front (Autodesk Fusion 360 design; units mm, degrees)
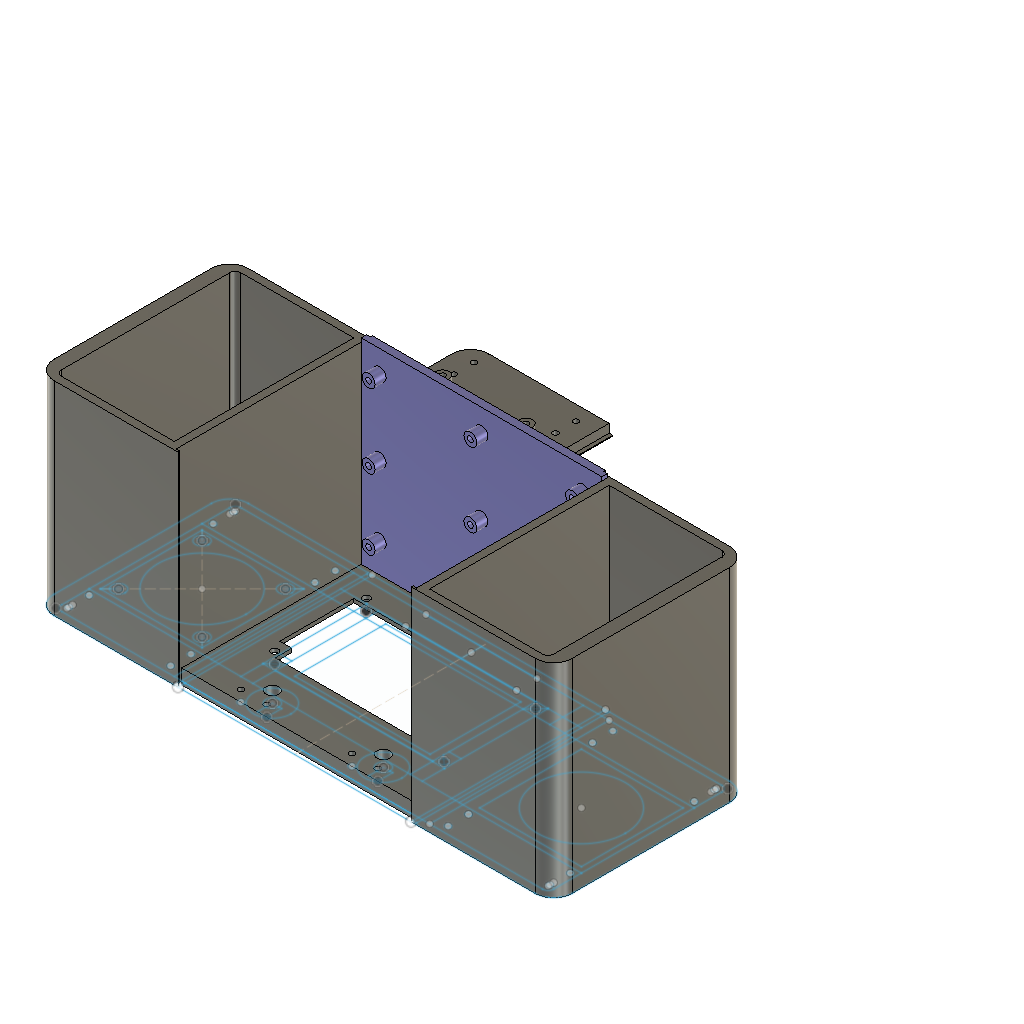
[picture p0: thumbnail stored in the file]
part number: 2026-10-08-07-20-58-243
sketch "Sketch1" plane through (0, 0, 0) normal (0, 0, 1) x axis (1, 0, 0)
  line L1 (260, -5) -> (20, -5)
  line L2 (270, -100) -> (270, -15)
  line L3 (20, -110) -> (260, -110)
  line L4 (210, -30) -> (265, -30)
  line L5 (210, -85) -> (210, -30)
  line L6 (265, -85) -> (210, -85)
  line L7 (265, -30) -> (265, -85)
  line L8 (70, -30) -> (15, -30)
  line L9 (70, -85) -> (70, -30)
  line L10 (15, -85) -> (70, -85)
  line L11 (15, -30) -> (15, -85)
  line L12 (187, -20) -> (89, -20)
  line L13 (187, -76) -> (187, -20)
  line L14 (89, -76) -> (187, -76)
  line L15 (89, -20) -> (89, -76)
  curve K1
  curve K2
  curve K3
  curve K4
  line L16 (95.5, -75.75) -> (180.5, -75.75)
  line L17 (95.5, -20.25) -> (95.5, -75.75)
  line L18 (180.5, -20.25) -> (95.5, -20.25)
  line L19 (180.5, -75.75) -> (180.5, -20.25)
  line L20 (176.5, -24.25) -> (103.5, -24.25)
  line L21 (176.5, -73.25) -> (176.5, -24.25)
  line L22 (103.5, -73.25) -> (176.5, -73.25)
  line L23 (103.5, -24.25) -> (103.5, -73.25)
  line L24 (10, -100) -> (10, -15)
  line L25 (140, -5) -> (140, -110)
  line L26 (75, -110) -> (75, -5)
  line L27 (205, -110) -> (205, -5)
  line L28 (77, -110) -> (77, -5)
  line L29 (203, -110) -> (203, -5)
  line L30 (203, -7) -> (77, -7)
  line L31 (203, -108) -> (77, -108)
  line L32 (70, -85) -> (15, -30)
  line L33 (70, -30) -> (15, -85)
  line L34 (19.9497, -34.9497) -> (15, -30)
  line L35 (65.0503, -34.9497) -> (70, -30)
  line L36 (19.9497, -80.0503) -> (15, -85)
  line L37 (65.0503, -80.0503) -> (70, -85)
  line L38 (176.5, -164.25) -> (103.5, -164.25)
  curve K5
  curve K6
  curve K7
  curve K8
  line L39 (187, -160) -> (89, -160)
  line L40 (14.9497, -174.9497) -> (10, -170)
  line L41 (14.9497, -220.0503) -> (10, -225)
  line L42 (65, -225) -> (65, -170)
  line L43 (60.0503, -220.0503) -> (65, -225)
  line L44 (95.5, -215.75) -> (180.5, -215.75)
  line L45 (203, -248) -> (77, -248)
  line L46 (270, -145) -> (10, -145)
  line L47 (10, -250) -> (270, -250)
  line L48 (103.5, -213.25) -> (176.5, -213.25)
  line L49 (77, -250) -> (77, -145)
  line L50 (180.5, -160.25) -> (95.5, -160.25)
  line L51 (203, -147) -> (77, -147)
  line L52 (89, -216) -> (187, -216)
  line L53 (10, -225) -> (65, -225)
  line L54 (215, -170) -> (270, -170)
  line L55 (75, -250) -> (75, -145)
  line L56 (65, -225) -> (10, -170)
  line L57 (95.5, -160.25) -> (95.5, -215.75)
  line L58 (176.5, -213.25) -> (176.5, -164.25)
  line L59 (140, -145) -> (140, -250)
  line L60 (205, -250) -> (205, -145)
  line L61 (270, -225) -> (215, -225)
  line L62 (103.5, -164.25) -> (103.5, -213.25)
  line L63 (0, -240) -> (0, -155)
  line L64 (187, -216) -> (187, -160)
  line L65 (89, -160) -> (89, -216)
  line L66 (65, -170) -> (10, -170)
  line L67 (60.0503, -174.9497) -> (65, -170)
  line L68 (65, -170) -> (10, -225)
  line L69 (203, -250) -> (203, -145)
  line L70 (10, -170) -> (10, -225)
  line L71 (280, -240) -> (280, -155)
  line L72 (215, -225) -> (215, -170)
  line L73 (180.5, -215.75) -> (180.5, -160.25)
  line L74 (270, -170) -> (270, -225)
  circle C1 centre (165, -92) radius 10
  circle C2 centre (115, -92) radius 10
  circle C3 centre (42.5, -57.5) radius 23.75
  circle C4 centre (237.5, -57.5) radius 23.75
  circle C5 centre (165, -92) radius 3.5
  circle C6 centre (115, -92) radius 3.5
  arc A1 centre (20, -15) radius 10 clockwise from (10, -15) to (20, -5)
  arc A2 centre (20, -100) radius 10 clockwise from (20, -110) to (10, -100)
  arc A3 centre (260, -100) radius 10 clockwise from (270, -100) to (260, -110)
  arc A4 centre (260, -15) radius 10 clockwise from (260, -5) to (270, -15)
  circle C7 centre (19.9497, -34.9497) radius 1.5
  circle C8 centre (65.0503, -34.9497) radius 1.5
  circle C9 centre (19.9497, -80.0503) radius 1.5
  circle C10 centre (65.0503, -80.0503) radius 1.5
  circle C11 centre (19.9497, -80.0503) radius 3.5
  circle C12 centre (65.0503, -80.0503) radius 3.5
  circle C13 centre (65.0503, -34.9497) radius 3.5
  circle C14 centre (19.9497, -34.9497) radius 3.5
  circle C15 centre (65, -102) radius 1.5
  circle C16 centre (20, -102) radius 1.5
  circle C17 centre (65, -91) radius 1.5
  circle C18 centre (20, -91) radius 1.5
  circle C19 centre (65, -13) radius 1.5
  circle C20 centre (20, -13) radius 1.5
  circle C21 centre (20, -24) radius 1.5
  circle C22 centre (65, -24) radius 1.5
  circle C23 centre (60.0503, -174.9497) radius 3.5
  circle C24 centre (65, -164) radius 1.5
  circle C25 centre (60.0503, -220.0503) radius 1.5
  circle C26 centre (10, -164) radius 1.5
  circle C27 centre (14.9497, -174.9497) radius 3.5
  arc A5 centre (10, -240) radius 10 clockwise from (10, -250) to (0, -240)
  circle C28 centre (10, -231) radius 1.5
  circle C29 centre (14.9497, -220.0503) radius 1.5
  circle C30 centre (10, -242) radius 1.5
  circle C31 centre (14.9497, -174.9497) radius 1.5
  circle C32 centre (14.9497, -220.0503) radius 3.5
  arc A6 centre (10, -155) radius 10 clockwise from (0, -155) to (10, -145)
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  point P40 (140, -110)
  point P41 (140, -5)
  point P42 (75, -5)
  point P43 (75, -110)
  point P44 (205, -5)
  point P45 (205, -110)
  point P50 (77, -7)
  point P51 (203, -7)
  point P52 (77, -108)
  point P53 (203, -108)
  point P54 (19.9497, -34.9497)
  point P58 (19.9497, -34.9497)
  point P55 (65.0503, -34.9497)
  point P59 (65.0503, -34.9497)
  point P56 (19.9497, -80.0503)
  point P60 (19.9497, -80.0503)
  point P57 (65.0503, -80.0503)
  point P61 (65.0503, -80.0503)
  point P97 (140, -250)
  point P98 (140, -145)
  point P122 (75, -145)
  point P123 (75, -250)
  point P103 (205, -145)
  point P146 (205, -250)
  point P137 (77, -147)
  point P136 (203, -147)
  point P92 (77, -248)
  point P124 (203, -248)
  point P85 (14.9497, -174.9497)
  point P119 (14.9497, -174.9497)
  point P86 (60.0503, -174.9497)
  point P120 (60.0503, -174.9497)
  point P87 (14.9497, -220.0503)
  point P147 (14.9497, -220.0503)
  point P77 (60.0503, -220.0503)
  point P117 (60.0503, -220.0503)
  point P2 (265, -30)
  point P3 (210, -30)
  point P5 (265, -85)
  point P6 (15, -30)
  point P7 (70, -30)
  point P9 (15, -85)
  point P10 (89, -20)
  point P11 (187, -20)
  point P13 (89, -76)
  point P22 (95.5, -20.25)
  point P23 (180.5, -20.25)
  point P21 (95.5, -75.75)
  point P24 (103.5, -24.25)
  point P25 (176.5, -24.25)
  point P27 (103.5, -73.25)
  point P8 (70, -85)
  point P93 (270, -170)
  point P94 (215, -170)
  point P96 (270, -225)
  point P88 (10, -170)
  point P89 (65, -170)
  point P91 (10, -225)
  point P80 (187, -160)
  point P84 (89, -160)
  point P81 (89, -216)
  point P76 (180.5, -160.25)
  point P78 (95.5, -160.25)
  point P75 (95.5, -215.75)
  point P130 (103.5, -164.25)
  point P132 (176.5, -164.25)
  point P131 (103.5, -213.25)
  point P90 (65, -225)
  horizontal L1
  vertical L2
  horizontal L4
  vertical L5
  horizontal L6
  vertical L7
  horizontal L8
  vertical L9
  horizontal L10
  vertical L11
  horizontal L12
  vertical L13
  horizontal L14
  vertical L15
  concentric C1 C5
  concentric C2 C6
  horizontal L16
  perpendicular L16 L17
  horizontal L20
  vertical L21
  horizontal L22
  vertical L23
  perpendicular L3 L24
  tangent L24 A1
  tangent L1 A1
  tangent L24 A2
  tangent L3 A2
  tangent L2 A3
  tangent L3 A3
  tangent L1 A4
  tangent L2 A4
  midpoint L3 P40
  midpoint L1 P41
  perpendicular L1 L25
  coincident L1 P42
  coincident L3 P43
  perpendicular L3 L26
  coincident L1 P44
  coincident L3 P45
  perpendicular L3 L27
  coincident L28 P50
  coincident L29 P51
  perpendicular L29 L30
  coincident L28 P52
  coincident L29 P53
  perpendicular L29 L31
  parallel L32 L34
  parallel L33 L35
  parallel L33 L36
  parallel L32 L37
  coincident P54 P58
  coincident P55 P59
  coincident P56 P60
  coincident P57 P61
  horizontal L46
  vertical L71
  horizontal L54
  vertical L72
  horizontal L61
  vertical L74
  horizontal L66
  vertical L42
  horizontal L53
  vertical L70
  horizontal L39
  vertical L64
  horizontal L52
  vertical L65
  horizontal L44
  perpendicular L44 L57
  horizontal L38
  vertical L58
  horizontal L48
  vertical L62
  perpendicular L47 L63
  tangent A6 L63
  tangent A6 L46
  tangent A5 L63
  tangent A5 L47
  midpoint P97 L47
  midpoint P98 L46
  perpendicular L46 L59
  coincident P122 L46
  coincident P123 L47
  perpendicular L47 L55
  coincident P103 L46
  coincident P146 L47
  perpendicular L47 L60
  coincident P137 L49
  coincident P136 L69
  perpendicular L51 L69
  coincident P92 L49
  coincident P124 L69
  perpendicular L45 L69
  parallel L40 L56
  parallel L67 L68
  parallel L41 L68
  parallel L43 L56
  coincident P85 P119
  coincident P86 P120
  coincident P87 P147
  coincident P77 P117
  dimension "d7" distance P2 P3 = 55
  dimension "d8" distance P2 P5 = 55
  dimension "d9" distance P6 P7 = 55
  dimension "d10" distance P6 P9 = 55
  dimension "d11" distance P10 P11 = 98
  dimension "d12" distance P10 P13 = 56
  dimension "d16" diameter C1 = 20
  dimension "d17" diameter C2 = 20
  dimension "d20" diameter C3 = 47.5
  dimension "d21" diameter C4 = 47.5
  dimension "d22" diameter C5 = 7
  dimension "d23" diameter C6 = 7
  dimension "d24" distance P22 P23 = 85
  dimension "d25" distance P21 P22 = 55.5
  dimension "d28" distance P24 P25 = 73
  dimension "d29" distance P24 P27 = 49
  dimension "d32" radius A1 = 10
  dimension "d33" radius A2 = 10
  dimension "d34" radius A3 = 10
  dimension "d35" radius A4 = 10
  dimension "d40" distance P6 P54 = 7
  dimension "d41" distance P7 P55 = 7
  dimension "d42" distance P9 P56 = 7
  dimension "d43" distance P8 P57 = 7
  dimension "d44" diameter C7 = 3
  dimension "d45" diameter C8 = 3
  dimension "d46" diameter C9 = 3
  dimension "d47" diameter C10 = 3
  dimension "d48" = 2
  dimension "d49" = 2
  dimension "d50" = 2
  dimension "d51" = 2
  dimension "d64" diameter C15 = 3
  dimension "d66" diameter C16 = 3
  dimension "d68" diameter C17 = 3
  dimension "d70" diameter C18 = 3
  dimension "d72" diameter C19 = 3
  dimension "d74" diameter C20 = 3
  dimension "d76" diameter C21 = 3
  dimension "d78" diameter C22 = 3
  dimension "d95" = 2
  dimension "d96" = 2
  dimension "d97" = 2
  dimension "d98" = 2
  dimension "d99" distance P93 P94 = 55
  dimension "d100" distance P93 P96 = 55
  dimension "d101" distance P88 P89 = 55
  dimension "d102" distance P88 P91 = 55
  dimension "d103" distance P80 P84 = 98
  dimension "d104" distance P81 P84 = 56
  dimension "d105" diameter = 20
  dimension "d106" diameter = 20
  dimension "d107" diameter = 47.5
  dimension "d108" diameter = 47.5
  dimension "d109" diameter = 7
  dimension "d110" diameter = 7
  dimension "d111" distance P76 P78 = 85
  dimension "d112" distance P75 P78 = 55.5
  dimension "d113" distance P130 P132 = 73
  dimension "d114" distance P130 P131 = 49
  dimension "d115" radius A6 = 10
  dimension "d116" radius A5 = 10
  dimension "d117" radius = 10
  dimension "d118" radius = 10
  dimension "d119" distance P85 P88 = 7
  dimension "d120" distance P86 P89 = 7
  dimension "d121" distance P87 P91 = 7
  dimension "d122" distance P90 P117 = 7
  dimension "d123" diameter C31 = 3
  dimension "d124" diameter = 3
  dimension "d125" diameter C29 = 3
  dimension "d126" diameter C25 = 3
  dimension "d127" diameter = 3
  dimension "d128" diameter C30 = 3
  dimension "d129" diameter = 3
  dimension "d130" diameter C28 = 3
  dimension "d131" diameter = 3
  dimension "d132" diameter = 3
  dimension "d133" diameter C26 = 3
  dimension "d134" diameter C24 = 3
  dimension "d144" distance L55 L60 = 130
  dimension "d145" distance L46 L47 = 105
  dimension "d18" Text1-Height = 6
  dimension "d93" Text2-Height = 6
extrude "Extrude3" new body sketch "Sketch1" profile of L1 L3 L8 L9 L10 L11 C3 L24 A1 A2 L26 L34 L35 L36 L37 C7 C8 C9 C10 C11 C12 C13 C14 C15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 along normal blind 5
extrude "Extrude4" add sketch "Sketch1" profile of L1 L3 L26 L28 along normal blind 0.4
extrude "Extrude7" cut sketch "Sketch1" profile of C15 C16 C17 C18 C19 C20 C21 C22 blind 3 from offset 2
extrude "Extrude8" add sketch "Sketch1" profile of C7 C8 C9 C10 C11 C12 C13 C14 along normal blind 12.5
extrude "Extrude9" new body sketch "Sketch1" along normal blind 5
extrude "Extrude10" add sketch "Sketch1" profile of L46 L47 L49 L55 along normal blind 0.4
extrude "Extrude11" add sketch "Sketch1" along normal blind 12.5
extrude "Extrude12" cut sketch "Sketch1" blind 3 from offset 2
sketch "Sketch2" plane through (0, 0, 0) normal (0, 0, 1) x axis (1, 0, 0)
  line L1 (10, -380) -> (270, -380)
  line L2 (270, -275) -> (10, -275)
  line L3 (270, -355) -> (215, -355)
  line L4 (89, -346) -> (187, -346)
  line L5 (0, -370) -> (0, -285)
  line L6 (176.5, -294.25) -> (103.5, -294.25)
  line L7 (65, -300) -> (10, -355)
  line L8 (60.0503, -350.0503) -> (65, -355)
  line L9 (95.5, -345.75) -> (180.5, -345.75)
  line L10 (103.5, -343.25) -> (176.5, -343.25)
  line L11 (180.5, -345.75) -> (180.5, -290.25)
  line L12 (89, -290) -> (89, -346)
  line L13 (187, -346) -> (187, -290)
  line L14 (65, -355) -> (10, -300)
  line L15 (77, -380) -> (77, -275)
  line L16 (187, -290) -> (89, -290)
  line L17 (65, -355) -> (65, -300)
  line L18 (10, -300) -> (10, -355)
  line L19 (215, -355) -> (215, -300)
  line L20 (203, -380) -> (203, -275)
  line L21 (280, -370) -> (280, -285)
  line L22 (180.5, -290.25) -> (95.5, -290.25)
  line L23 (205, -380) -> (205, -275)
  line L24 (176.5, -343.25) -> (176.5, -294.25)
  line L25 (75, -380) -> (75, -275)
  line L26 (95.5, -290.25) -> (95.5, -345.75)
  line L27 (215, -300) -> (270, -300)
  line L28 (140, -275) -> (140, -380)
  line L29 (103.5, -294.25) -> (103.5, -343.25)
  line L30 (10, -355) -> (65, -355)
  line L31 (270, -300) -> (270, -355)
  line L32 (14.9497, -350.0503) -> (10, -355)
  line L33 (65, -300) -> (10, -300)
  line L34 (14.9497, -304.9497) -> (10, -300)
  line L35 (60.0503, -304.9497) -> (65, -300)
  line L36 (270, -279) -> (10, -279)
  line L37 (273, -297) -> (273, -282)
  line L38 (7, -297) -> (273, -297)
  line L39 (7, -282) -> (7, -297)
  line L40 (195, -297) -> (195, -279)
  line L41 (95.5, -297) -> (89, -290)
  line L42 (180.5, -297) -> (187, -290)
  line L43 (75, -290) -> (89, -290)
  line L44 (205, -290) -> (187, -290)
  line L45 (140, -290) -> (140, -279)
  line L46 (110, -279) -> (170, -279)
  line L47 (170, -290) -> (110, -290)
  line L48 (7, -358) -> (7, -297)
  line L49 (273, -358) -> (7, -358)
  line L50 (273, -373) -> (273, -358)
  line L51 (10, -376) -> (270, -376)
  line L52 (7, -358) -> (7, -373)
  line L53 (73, -358) -> (73, -297)
  line L54 (207, -358) -> (207, -297)
  line L55 (89, -358) -> (89, -346)
  line L56 (187, -358) -> (187, -346)
  line L57 (95.5, -340) -> (89, -346)
  line L58 (180.5, -340) -> (187, -346)
  line L59 (95.5, -337) -> (89, -337)
  line L60 (95.5, -358) -> (95.5, -345.75)
  line L61 (180.5, -337) -> (187, -337)
  line L62 (180.5, -358) -> (180.5, -345.75)
  line L63 (110, -370) -> (110, -362)
  line L64 (115, -362) -> (110, -362)
  line L65 (115, -370) -> (115, -362)
  line L66 (110, -370) -> (115, -370)
  line L67 (175, -362) -> (170, -362)
  line L68 (175, -370) -> (175, -362)
  line L69 (170, -370) -> (175, -370)
  line L70 (170, -362) -> (170, -370)
  line L71 (273, -358) -> (273, -297)
  line L72 (77, -276) -> (75, -276)
  line L73 (71, -376) -> (71, -279)
  line L74 (77, -379) -> (75, -379)
  line L75 (203, -276) -> (205, -276)
  line L76 (203, -379) -> (205, -379)
  line L77 (209, -376) -> (209, -279)
  circle C1 centre (170, -362) radius 3.5
  circle C2 centre (110, -362) radius 3.5
  circle C3 centre (10, -372) radius 1.4
  circle C4 centre (242.5, -327.5) radius 23.75
  circle C5 centre (37.5, -327.5) radius 23.75
  arc A1 centre (270, -370) radius 10 clockwise from (280, -370) to (270, -380)
  circle C6 centre (170, -362) radius 10
  circle C7 centre (14.9497, -350.0503) radius 3.5
  arc A2 centre (270, -285) radius 10 clockwise from (270, -275) to (280, -285)
  circle C8 centre (10, -361) radius 1.4
  arc A3 centre (10, -370) radius 10 clockwise from (10, -380) to (0, -370)
  circle C9 centre (110, -362) radius 10
  circle C10 centre (60.0503, -350.0503) radius 3.5
  circle C11 centre (65, -372) radius 1.4
  circle C12 centre (60.0503, -350.0503) radius 1.5
  circle C13 centre (65, -361) radius 1.4
  circle C14 centre (14.9497, -350.0503) radius 1.5
  circle C15 centre (60.0503, -304.9497) radius 1.5
  arc A4 centre (10, -285) radius 10 clockwise from (0, -285) to (10, -275)
  circle C16 centre (14.9497, -304.9497) radius 3.5
  circle C17 centre (60.0503, -304.9497) radius 3.5
  circle C18 centre (14.9497, -304.9497) radius 1.5
  circle C19 centre (270, -294) radius 1.4
  circle C20 centre (270, -283) radius 1.4
  circle C21 centre (215, -294) radius 1.4
  circle C22 centre (215, -283) radius 1.4
  circle C23 centre (215, -361) radius 1.4
  circle C24 centre (215, -372) radius 1.4
  circle C25 centre (270, -361) radius 1.4
  circle C26 centre (270, -372) radius 1.4
  circle C27 centre (10, -283) radius 1.4
  circle C28 centre (10, -294) radius 1.4
  circle C29 centre (65, -283) radius 1.4
  circle C30 centre (65, -294) radius 1.4
  arc A5 centre (10, -282) radius 3 clockwise from (7, -282) to (10, -279)
  arc A6 centre (270, -282) radius 3 clockwise from (270, -279) to (273, -282)
  circle C31 centre (92.25, -293.5) radius 2
  circle C32 centre (183.75, -293.5) radius 2
  arc A7 centre (270, -373) radius 3 clockwise from (273, -373) to (270, -376)
  arc A8 centre (10, -373) radius 3 clockwise from (10, -376) to (7, -373)
  circle C33 centre (92.25, -343) radius 2
  circle C34 centre (183.75, -343) radius 2
  circle C35 centre (115, -370) radius 1.5
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  point P40 (140, -380)
  point P38 (140, -275)
  point P46 (75, -275)
  point P45 (75, -380)
  point P34 (205, -275)
  point P22 (205, -380)
  point P47 (14.9497, -304.9497)
  point P65 (14.9497, -304.9497)
  point P27 (60.0503, -304.9497)
  point P48 (60.0503, -304.9497)
  point P20 (14.9497, -350.0503)
  point P28 (14.9497, -350.0503)
  point P17 (60.0503, -350.0503)
  point P53 (60.0503, -350.0503)
  point P82 (195, -279)
  point P83 (195, -297)
  point P78 (7, -279)
  point P79 (273, -279)
  point P90 (95.5, -297)
  point P91 (92.25, -293.5)
  point P92 (180.5, -297)
  point P93 (183.75, -293.5)
  point P94 (75, -290)
  point P95 (205, -290)
  point P96 (140, -279)
  point P97 (140, -290)
  point P105 (7, -376)
  point P112 (73, -297)
  point P113 (73, -358)
  point P114 (207, -297)
  point P115 (207, -358)
  point P116 (89, -358)
  point P117 (187, -358)
  point P118 (95.5, -340)
  point P119 (92.25, -343)
  point P120 (180.5, -340)
  point P121 (183.75, -343)
  point P122 (89, -337)
  point P123 (95.5, -337)
  point P124 (95.5, -358)
  point P125 (187, -337)
  point P126 (180.5, -337)
  point P127 (180.5, -358)
  point P9 (110, -362)
  point P128 (110, -362)
  point P131 (115, -370)
  point P132 (115, -370)
  point P39 (170, -362)
  point P134 (170, -362)
  point P136 (175, -370)
  point P138 (175, -370)
  point P140 (75, -276)
  point P141 (77, -276)
  point P142 (71, -279)
  point P143 (71, -376)
  point P144 (75, -379)
  point P145 (77, -379)
  point P146 (205, -276)
  point P147 (203, -276)
  point P148 (205, -379)
  point P149 (203, -379)
  point P2 (215, -300)
  point P8 (270, -300)
  point P4 (270, -355)
  point P5 (65, -300)
  point P26 (10, -300)
  point P7 (10, -355)
  point P6 (65, -355)
  point P103 (7, -358)
  point P135 (175, -362)
  point P137 (170, -370)
  horizontal L2
  vertical L21
  horizontal L27
  vertical L19
  horizontal L3
  vertical L31
  horizontal L33
  vertical L17
  horizontal L30
  vertical L18
  horizontal L16
  vertical L13
  horizontal L4
  vertical L12
  concentric C1 C6
  concentric C2 C9
  horizontal L9
  perpendicular L9 L26
  horizontal L6
  vertical L24
  horizontal L10
  vertical L29
  perpendicular L1 L5
  tangent L5 A4
  tangent L2 A4
  tangent L5 A3
  tangent L1 A3
  tangent A1 L21
  tangent L1 A1
  tangent L2 A2
  tangent A2 L21
  midpoint P40 L1
  midpoint P38 L2
  perpendicular L2 L28
  coincident P46 L2
  coincident P45 L1
  perpendicular L1 L25
  coincident P34 L2
  coincident P22 L1
  perpendicular L1 L23
  parallel L14 L34
  parallel L7 L35
  parallel L7 L32
  parallel L8 L14
  coincident P47 P65
  coincident P27 P48
  coincident P20 P28
  coincident P17 P53
  horizontal L36
  vertical L37
  horizontal L38
  vertical L39
  coincident L36 P82
  coincident L38 P83
  perpendicular L38 L40
  coincident P78 L36
  coincident P78 L39
  tangent L36 A5
  tangent L39 A5
  coincident P79 L36
  coincident P79 L37
  tangent L36 A6
  tangent L37 A6
  coincident L26 P90
  coincident L38 P90
  midpoint L41 P91
  coincident L11 P92
  coincident L38 P92
  midpoint L42 P93
  coincident L25 P94
  perpendicular L25 L43
  coincident L23 P95
  perpendicular L23 L44
  midpoint L36 P96
  coincident L16 P97
  coincident L28 P97
  horizontal L46
  parallel L46 L47
  perpendicular L38 L48
  horizontal L49
  vertical L50
  horizontal L51
  vertical L52
  tangent L50 A7
  tangent L51 A7
  coincident P105 L51
  coincident P105 L52
  tangent L51 A8
  tangent L52 A8
  coincident L38 P112
  coincident L49 P113
  perpendicular L49 L53
  coincident L38 P114
  coincident L49 P115
  perpendicular L49 L54
  coincident L49 P116
  perpendicular L49 L55
  coincident L49 P117
  perpendicular L49 L56
  coincident L26 P118
  midpoint L57 P119
  coincident L11 P120
  midpoint L58 P121
  coincident L12 P122
  coincident L26 P123
  perpendicular L26 L59
  coincident L49 P124
  perpendicular L49 L60
  coincident L13 P125
  coincident L11 P126
  perpendicular L11 L61
  coincident L49 P127
  perpendicular L49 L62
  coincident P9 P128
  perpendicular L51 L63
  perpendicular L63 L64
  perpendicular L51 L65
  perpendicular L63 L66
  coincident P131 P132
  horizontal L67
  vertical L68
  horizontal L69
  vertical L70
  coincident P39 P134
  coincident P136 P138
  perpendicular L49 L71
  coincident L25 P140
  coincident L15 P141
  perpendicular L15 L72
  coincident L36 P142
  coincident L51 P143
  perpendicular L51 L73
  coincident L25 P144
  coincident L15 P145
  perpendicular L15 L74
  coincident L23 P146
  coincident L20 P147
  perpendicular L20 L75
  coincident L23 P148
  coincident L20 P149
  perpendicular L20 L76
  perpendicular L38 L77
  dimension "d148" = 2
  dimension "d149" = 2
  dimension "d150" = 2
  dimension "d151" = 2
  dimension "d152" distance P2 P8 = 55
  dimension "d153" distance P4 P8 = 55
  dimension "d154" distance P5 P26 = 55
  dimension "d155" distance P7 P26 = 55
  dimension "d158" diameter C6 = 20
  dimension "d159" diameter C9 = 20
  dimension "d160" diameter C5 = 47.5
  dimension "d161" diameter C4 = 47.5
  dimension "d162" diameter C1 = 7
  dimension "d163" diameter C2 = 7
  dimension "d168" radius A4 = 10
  dimension "d169" radius A3 = 10
  dimension "d170" radius A1 = 10
  dimension "d171" radius A2 = 10
  dimension "d172" distance P26 P65 = 7
  dimension "d173" distance P5 P27 = 7
  dimension "d174" distance P7 P28 = 7
  dimension "d175" distance P6 P53 = 7
  dimension "d176" diameter C18 = 3
  dimension "d177" diameter C15 = 3
  dimension "d178" diameter C14 = 3
  dimension "d179" diameter C12 = 3
  dimension "d180" diameter C11 = 2.8
  dimension "d181" diameter C3 = 2.8
  dimension "d182" diameter C13 = 2.8
  dimension "d183" diameter C8 = 2.8
  dimension "d188" distance L23 L25 = 130
  dimension "d189" distance L1 L2 = 105
  dimension "d191" diameter C19 = 2.8
  dimension "d193" diameter C20 = 2.8
  dimension "d195" diameter C21 = 2.8
  dimension "d197" diameter C22 = 2.8
  dimension "d199" diameter C23 = 2.8
  dimension "d201" diameter C24 = 2.8
  dimension "d203" diameter C25 = 2.8
  dimension "d205" diameter C26 = 2.8
  dimension "d206" diameter C27 = 2.8
  dimension "d207" diameter C28 = 2.8
  dimension "d208" diameter C29 = 2.8
  dimension "d209" diameter C30 = 2.8
  dimension "d210" distance P78 P79 = 266
  dimension "d218" radius A5 = 3
  dimension "d219" radius A6 = 3
  dimension "d220" diameter C31 = 4
  dimension "d221" diameter C32 = 4
  dimension "d256" distance P103 P105 = 18
  dimension "d257" radius A7 = 3
  dimension "d258" radius A8 = 3
  dimension "d261" diameter C33 = 4
  dimension "d262" diameter C34 = 4
  dimension "d263" diameter C35 = 3
  dimension "d264" diameter = 3
  dimension "d265" distance P134 P135 = 5
  dimension "d266" distance P134 P137 = 8
  dimension "d267" diameter = 3
  dimension "d268" diameter = 3
extrude "Extrude17" new body sketch "Sketch2" profile of C3 C8 L23 L25 C11 C13 C19 C20 C21 C22 C23 C24 C25 C26 C27 C28 C29 C30 L36 L37 L38 L39 A5 A6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 along normal blind 4
extrude "Extrude18" new body sketch "Sketch2" profile of C1 C2 L15 L16 C6 L20 L23 L25 C9 L36 L40 L43 L44 L45 L46 L47 L49 L51 against normal blind 2 and along normal blind 4
extrude "Extrude19" add of existing geometry blind 2
extrude "Extrude21" add sketch "Sketch2" profile of C3 C8 C11 C13 C19 C20 C21 C22 C23 C24 C25 C26 C27 C28 C29 C30 against normal blind 2.5
extrude "Extrude25" add sketch "Sketch2" profile of L23 L25 L38 L49 L53 L54 along normal blind 6
extrude "Extrude26" cut sketch "Sketch2" along normal blind 6
extrude "Extrude20" add sketch "Sketch2" profile of L4 L6 L11 L12 L13 L15 L16 C6 L20 L22 L23 L24 L25 L26 L29 C9 L38 L40 L41 C31 L42 C32 L43 L44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 blind 2 from offset 4
extrude "Extrude27" new body sketch "Sketch2" profile of L1 L2 L5 L15 L25 A3 A4 L36 L38 L39 A5 L48 L49 L51 L52 A8 L53 L72 L73 L74 along normal blind 110
combine "Combine2"
extrude "Extrude28" new body sketch "Sketch2" profile of L1 L2 A1 A2 L20 L21 L23 L36 L37 L38 A6 L49 L50 L51 A7 L54 L71 L75 L76 L77 along normal blind 110
combine "Combine3"
extrude "Extrude29" new body sketch "Sketch2" profile of L2 L15 L20 L23 L25 L36 L46 L72 L75 along normal blind 112
sketch "Sketch3" plane through (0, -279, 0) normal (0, -1, 0) x axis (1, 0, 0)
  line L1 (205, 0) -> (75, 0)
  line L2 (205, 112) -> (205, 0)
  line L3 (75, 112) -> (205, 112)
  line L4 (75, 0) -> (75, 112)
  circle C1 centre (85, 100) radius 3.5
  circle C2 centre (85, 100) radius 1.5
  circle C3 centre (195, 100) radius 3.5
  circle C4 centre (85, 22) radius 3.5
  circle C5 centre (195, 22) radius 3.5
  circle C6 centre (85, 60) radius 3.5
  circle C7 centre (195, 60) radius 3.5
  circle C8 centre (140, 60) radius 3.5
  circle C9 centre (140, 100) radius 3.5
  circle C10 centre (140, 22) radius 3.5
  circle C11 centre (85, 60) radius 1.5
  circle C12 centre (85, 22) radius 1.5
  circle C13 centre (140, 22) radius 1.5
  circle C14 centre (140, 60) radius 1.5
  circle C15 centre (140, 100) radius 1.5
  circle C16 centre (195, 100) radius 1.5
  circle C17 centre (195, 60) radius 1.5
  circle C18 centre (195, 22) radius 1.5
  concentric C1 C2
  concentric C6 C11
  concentric C4 C12
  concentric C10 C13
  concentric C8 C14
  concentric C9 C15
  concentric C3 C16
  concentric C7 C17
  concentric C5 C18
  dimension "d277" diameter C1 = 7
  dimension "d278" diameter C2 = 3
  dimension "d279" diameter C3 = 7
  dimension "d280" diameter C4 = 7
  dimension "d281" diameter C5 = 7
  dimension "d282" diameter C6 = 7
  dimension "d283" diameter C7 = 7
  dimension "d284" diameter C8 = 7
  dimension "d285" diameter C9 = 7
  dimension "d286" diameter C10 = 7
  dimension "d287" diameter C11 = 3
  dimension "d288" diameter C12 = 3
  dimension "d289" diameter C13 = 3
  dimension "d290" diameter C14 = 3
  dimension "d291" diameter C15 = 3
  dimension "d292" diameter C16 = 3
  dimension "d293" diameter C17 = 3
  dimension "d294" diameter C18 = 3
extrude "Extrude30" add sketch "Sketch3" profile of C1 C2 C3 C4 C5 C6 C7 C8 C9 C10 C11 C12 C13 C14 C15 C16 C17 C18 along normal blind 6
sketch "Sketch4" plane through (0, 0, 0) normal (0, 0, 1) x axis (1, 0, 0)
  line L1 (75, -580) -> (75, -475)
  line L2 (7, -482) -> (7, -497)
  line L3 (73, -558) -> (73, -497)
  line L4 (77, -580) -> (77, -475)
  line L5 (71, -576) -> (71, -479)
  line L6 (77, -476) -> (75, -476)
  line L7 (77, -579) -> (75, -579)
  line L8 (7, -558) -> (7, -573)
  line L9 (273, -558) -> (273, -497)
  line L10 (0, -570) -> (0, -485)
  line L11 (280, -570) -> (280, -485)
  line L12 (203, -476) -> (205, -476)
  line L13 (7, -558) -> (7, -497)
  line L14 (273, -573) -> (273, -558)
  line L15 (207, -558) -> (207, -497)
  line L16 (203, -580) -> (203, -475)
  line L17 (273, -497) -> (273, -482)
  line L18 (203, -579) -> (205, -579)
  line L19 (205, -580) -> (205, -475)
  line L20 (209, -576) -> (209, -479)
  line L21 (270, -475) -> (10, -475)
  line L22 (273, -558) -> (7, -558)
  line L23 (10, -580) -> (270, -580)
  line L24 (270, -479) -> (10, -479)
  line L25 (10, -576) -> (270, -576)
  line L26 (7, -497) -> (273, -497)
  curve K1 (37.5, -559) -> (37.5, -496)
  curve K2 (65.5, -527.5) -> (9.5, -527.5)
  circle C1 centre (270, -494) radius 1.4
  circle C2 centre (65, -572) radius 1.4
  circle C3 centre (270, -483) radius 1.4
  arc A1 centre (10, -570) radius 10 clockwise from (10, -580) to (0, -570)
  circle C4 centre (65, -561) radius 1.4
  circle C5 centre (65, -483) radius 1.4
  circle C6 centre (65, -494) radius 1.4
  circle C7 centre (270, -572) radius 1.4
  arc A2 centre (10, -573) radius 3 clockwise from (10, -576) to (7, -573)
  arc A3 centre (270, -482) radius 3 clockwise from (270, -479) to (273, -482)
  circle C8 centre (215, -494) radius 1.4
  arc A4 centre (270, -485) radius 10 clockwise from (270, -475) to (280, -485)
  circle C9 centre (10, -494) radius 1.4
  circle C10 centre (10, -561) radius 1.4
  arc A5 centre (10, -482) radius 3 clockwise from (7, -482) to (10, -479)
  circle C11 centre (215, -483) radius 1.4
  circle C12 centre (215, -572) radius 1.4
  circle C13 centre (270, -561) radius 1.4
  circle C14 centre (215, -561) radius 1.4
  arc A6 centre (10, -485) radius 10 clockwise from (0, -485) to (10, -475)
  circle C15 centre (10, -483) radius 1.4
  circle C16 centre (10, -572) radius 1.4
  arc A7 centre (270, -573) radius 3 clockwise from (273, -573) to (270, -576)
  arc A8 centre (270, -570) radius 10 clockwise from (280, -570) to (270, -580)
  circle C17 centre (242.5, -527.5) radius 23.75
  circle C18 centre (37.5, -527.5) radius 23.75
  closed curve K3 centre (37.5, -527.5)
  point P15 (75, -475)
  point P14 (75, -580)
  point P55 (205, -475)
  point P8 (205, -580)
  point P70 (7, -479)
  point P66 (273, -479)
  point P71 (7, -576)
  point P63 (73, -497)
  point P60 (73, -558)
  point P62 (207, -497)
  point P64 (207, -558)
  point P42 (75, -476)
  point P12 (77, -476)
  point P73 (71, -479)
  point P74 (71, -576)
  point P36 (75, -579)
  point P37 (77, -579)
  point P38 (205, -476)
  point P35 (203, -476)
  point P3 (205, -579)
  point P2 (203, -579)
  point P76 (37.5, -496)
  point P77 (37.5, -559)
  point P78 (9.5, -527.5)
  point P79 (65.5, -527.5)
  horizontal L21
  vertical L11
  perpendicular L10 L23
  tangent L10 A6
  tangent A6 L21
  tangent A1 L10
  tangent A1 L23
  tangent L11 A8
  tangent A8 L23
  tangent A4 L21
  tangent A4 L11
  coincident P15 L21
  coincident P14 L23
  perpendicular L1 L23
  coincident P55 L21
  coincident P8 L23
  perpendicular L19 L23
  horizontal L24
  vertical L17
  horizontal L26
  vertical L2
  coincident P70 L24
  coincident P70 L2
  tangent A5 L24
  tangent L2 A5
  coincident P66 L24
  coincident P66 L17
  tangent A3 L24
  tangent A3 L17
  perpendicular L13 L26
  horizontal L22
  vertical L14
  horizontal L25
  vertical L8
  tangent L14 A7
  tangent A7 L25
  coincident P71 L25
  coincident P71 L8
  tangent A2 L25
  tangent A2 L8
  coincident P63 L26
  coincident P60 L22
  perpendicular L3 L22
  coincident P62 L26
  coincident P64 L22
  perpendicular L15 L22
  perpendicular L9 L22
  coincident P42 L1
  coincident P12 L4
  perpendicular L4 L6
  coincident P73 L24
  coincident P74 L25
  perpendicular L5 L25
  coincident P36 L1
  coincident P37 L4
  perpendicular L4 L7
  coincident P38 L19
  coincident P35 L16
  perpendicular L12 L16
  coincident P3 L19
  coincident P2 L16
  perpendicular L16 L18
  perpendicular L20 L26
  coincident K3 P76
  coincident K3 P77
  coincident K3 P78
  coincident K3 P79
  concentric C18 K3
  parallel L13 K1
  dimension "d359" distance K3 = 63
  dimension "d360" = 56
  dimension "d361" = 2
extrude "Extrude31" new body sketch "Sketch4" profile of L1 C1 C2 C3 L2 A1 L3 C4 L4 C5 C6 L5 L6 C7 L7 A2 A3 C8 A4 L8 L9 L10 C9 L11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 along normal blind 5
